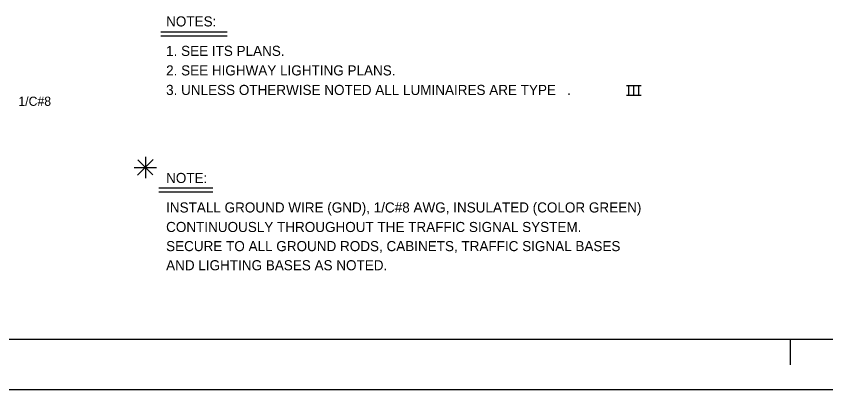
# Model space of a CAD drawing. Extents: x 488740 to 507913, y 466518 to 497949.
# Drawn here: x 507908.531 to 507909.198, y 496046.406 to 496046.714 of the extents above; entities that cross this region are included whole.
import ezdxf

# ---------------------------------------------------------------- set-up
doc = ezdxf.new("R2010")
doc.units = 0
doc.layers.add('1', color=7, linetype='Continuous')
doc.layers.add('9', color=7, linetype='Continuous')

msp = doc.modelspace()

# ---------------------------------------------------------------- linework, layer by layer
at = {"layer": '1'}
for p, q in [((507907.8773, 496046.44783), (507910.6273, 496046.44783)), ((507909.16929, 496046.42684), (507909.16929, 496046.44783)), ((507910.63583, 496046.40617), (507907.72408, 496046.40617))]:
    msp.add_line(p, q, dxfattribs=at)
at = {"layer": '9'}
for p, q in [((507908.65059, 496046.70084), (507908.70505, 496046.70084)), ((507908.65059, 496046.69756), (507908.70505, 496046.69756)), ((507909.03427, 496046.65682), (507909.0464, 496046.65682)), ((507909.0362, 496046.64892), (507909.0362, 496046.65682)), ((507909.04033, 496046.64892), (507909.04033, 496046.65682)), ((507909.04447, 496046.64892), (507909.04447, 496046.65682)), ((507909.03427, 496046.64892), (507909.0464, 496046.64892)), ((507908.63777, 496046.59807), (507908.63777, 496046.58057)), ((507908.63131, 496046.58286), (507908.64424, 496046.59578)), ((507908.63159, 496046.59551), (507908.64396, 496046.58314)), ((507908.62864, 496046.58932), (507908.64691, 496046.58932)), ((507908.64895, 496046.57251), (507908.69324, 496046.57251)), ((507908.64895, 496046.56923), (507908.69324, 496046.56923))]:
    msp.add_line(p, q, dxfattribs=at)

# ---------------------------------------------------------------- texts
for s, height, p in [('NOTES:', 0.008313, (507908.65486, 496046.70538)), ('1. SEE ITS PLANS.', 0.008313, (507908.65486, 496046.6811)), ('2. SEE HIGHWAY LIGHTING PLANS.', 0.008313, (507908.65486, 496046.66503)), ('3. UNLESS OTHERWISE NOTED ALL LUMINAIRES ARE TYPE   .', 0.008313, (507908.65486, 496046.64895)), ('1/C#8', 0.007545, (507908.53316, 496046.64)), ('NOTE:', 0.008313, (507908.65486, 496046.57644)), ('INSTALL GROUND WIRE (GND), 1/C#8 AWG, INSULATED (COLOR GREEN)', 0.008313, (507908.65486, 496046.55217)), ('CONTINUOUSLY THROUGHOUT THE TRAFFIC SIGNAL SYSTEM.', 0.008313, (507908.65486, 496046.53609)), ('SECURE TO ALL GROUND RODS, CABINETS, TRAFFIC SIGNAL BASES', 0.008313, (507908.65486, 496046.52034)), ('AND LIGHTING BASES AS NOTED.', 0.008313, (507908.65486, 496046.50459))]:
    msp.add_text(s, height=height, dxfattribs=at).set_placement(p)

doc.saveas('drawing.dxf')
